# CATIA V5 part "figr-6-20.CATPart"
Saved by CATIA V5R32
Part number: Part1
Bounding box of the stored display mesh (mm): x 0 to 150, y -70 to 70, z -150 to 69.804
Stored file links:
  D:\PROJECTS\Project 2022\CATIA V5 6R 2022\Resources\Part Files\c06_catia_v5_6r2022_prt\figr-6-20.CATPart
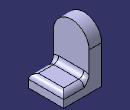
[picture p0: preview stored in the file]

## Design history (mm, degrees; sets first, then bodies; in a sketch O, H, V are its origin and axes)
Body1 (main body)
  Sketch1 on yz-plane, origin (0, 0, 0), H (0, 1, 0), V (0, 0, 1)
    arc A1 centre (0, 0) radius 70 from (70, 0) to (-70, 0) ccw
    point P1 (70, 0)
    point P2 (-70, 0)
    line L1 (-70, 0) -> (-70, -150)
    line L2 (-70, -150) -> (70, -150)
    line L3 (70, -150) -> (70, 0)
    construction circle A2 centre (0, 0) radius 37.5
    radius A1 = 70
    radius A2 = 37.5
    distance O L2 = 150
    coincidence: P1 H, P2 H
    tangency: L1 A1, L3 A1
    horizontal: L2 H
  Pad1: profile Sketch1, direction (1, 0, 0), length 50
  Sketch2 on face of Pad1, origin (50, 0, 0), H (0, 1, 0), V (0, 0, 1)
    line L1 (-70, -150) -> (70, -150)
    line L2 (70, -150) -> (70, -100)
    line L3 (70, -100) -> (-70, -100)
    line L4 (-70, -100) -> (-70, -150)
    reference projected line E1 (-70, -150) -> (70, -150) from edge [face of Pad1 | face of Pad1]
    reference projected line E2 (-70, 0) -> (-70, -150) from edge [face of Pad1 | face of Pad1]
    reference projected line E3 (70, -150) -> (70, 0) from edge [face of Pad1 | face of Pad1]
    length L2 = 50
    horizontal: L1 H, L3 H
    vertical: L2 V, L4 V
    coincidence: L1 E1, E2 L4, L2 E3
  Pad2: profile Sketch2, direction (1, 0, 0), length 100
  Fillet1: radius 20, on face of Pad2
